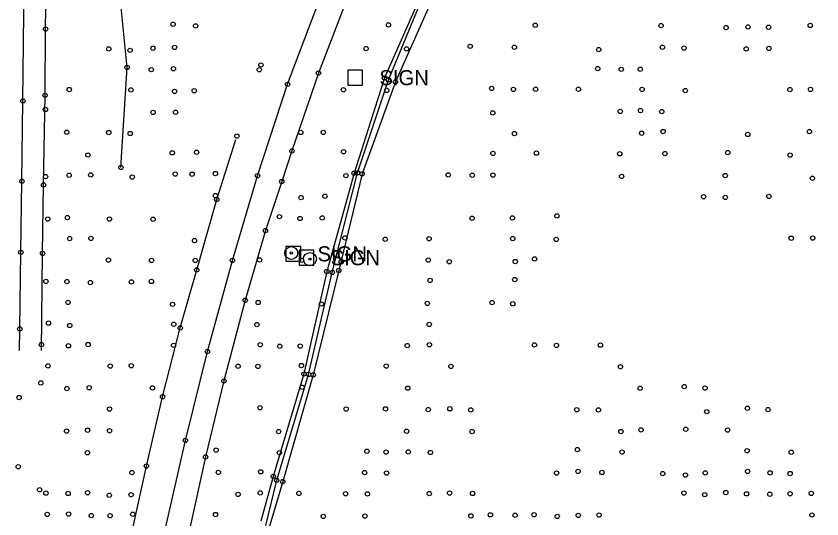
# Model space of a CAD drawing. Extents: x 20503438 to 20508873, y 7964251 to 7984667.
# Drawn here: x 20506713.1 to 20507086.3, y 7969482.5 to 7969715.3 of the extents above; entities that cross this region are included whole.
import ezdxf

# ---------------------------------------------------------------- set-up
doc = ezdxf.new("R2010")
doc.units = 0
for name, color, linetype in [('SurBreakLine', 7, 'Continuous'), ('SurConcreteSlab', 7, 'Continuous'), ('SurDrainageArrowDown', 7, 'Continuous'), ('SurEdgeRoadPaved', 7, 'Continuous'), ('SurEdgeShoulderPaved', 7, 'Continuous'), ('SurRoadPoints', 7, 'Continuous'), ('SurSurveyPoints', 7, 'Continuous')]:
    doc.layers.add(name, color=color, linetype=linetype)

msp = doc.modelspace()

# ---------------------------------------------------------------- linework, layer by layer
at = {"layer": 'SurBreakLine'}
for points in [[(20507072.22, 7970031.81), (20507044.65, 7969983.45), (20507017.24, 7969942.09), (20506993.08, 7969899.77), (20506969.73, 7969857.18), (20506943.8, 7969809.14), (20506917.86, 7969765.01), (20506900.22, 7969724.24), (20506883.74, 7969686.63), (20506869.66, 7969642.53), (20506857.03, 7969597), (20506846.45, 7969549.54), (20506832.21, 7969502.12), (20506826.5, 7969481.38)], [(20507077.67, 7970029.62), (20507050.22, 7969980.63), (20507024.17, 7969937.47), (20506998.98, 7969896.23), (20506975.04, 7969854.03), (20506947.28, 7969804.04), (20506923.35, 7969761.61), (20506905.03, 7969721.23), (20506888.8, 7969684.78), (20506873.33, 7969642.22), (20506862.58, 7969597.47), (20506850.72, 7969549.13), (20506836.64, 7969499.73), (20506830.12, 7969478.04)]]:
    msp.add_lwpolyline(points, dxfattribs=at)
at = {"layer": 'SurConcreteSlab'}
for points in [[(20506782.03, 7969476.8), (20506791.56, 7969518.77), (20506801.71, 7969559.92), (20506813.33, 7969602.11), (20506824.94, 7969641.33), (20506838.85, 7969683.67), (20506855.36, 7969727.47), (20506871.04, 7969767.26), (20506887.39, 7969806.48), (20506907.03, 7969849.3), (20506926.87, 7969889.92), (20506946.4, 7969927.42), (20506964.13, 7969959.84), (20506998.31, 7970022.29), (20507028.85, 7970078.15), (20507050.93, 7970118.98), (20507063.43, 7970141.95), (20507094.89, 7970195.02), (20507112.55, 7970224.35), (20507146.84, 7970287.64), (20507180.2, 7970349.4), (20507227.5, 7970437.73), (20507263.67, 7970507.83), (20507275.78, 7970531.85)], [(20507015.79, 7970022.74), (20506988.66, 7969972.82), (20506974.4, 7969946.87), (20506957.8, 7969916.38), (20506943.98, 7969890.96), (20506942.58, 7969888.39), (20506939.78, 7969883.25), (20506912.31, 7969832.46), (20506905.2, 7969817.2), (20506894.52, 7969794.31), (20506880.24, 7969759.41), (20506853.16, 7969688.88), (20506840.87, 7969652.86), (20506836.17, 7969638.67), (20506828.63, 7969615.96), (20506819.26, 7969583.67), (20506809.41, 7969546.3), (20506800.9, 7969511.15), (20506793, 7969475.34)]]:
    msp.add_lwpolyline(points, dxfattribs=at)
at = {"layer": 'SurDrainageArrowDown'}
for points in [[(20506828.82, 7969479.38), (20506833.81, 7969500.36), (20506848.56, 7969549.36), (20506859.54, 7969596.56), (20506871.26, 7969642.69), (20506885.58, 7969685.72), (20506901.36, 7969723.92), (20506920.9, 7969764.04), (20506945.51, 7969806.46), (20506972.6, 7969855.74), (20506995.89, 7969898.43), (20507018.3, 7969939.97), (20507047.05, 7969981.99), (20507075.27, 7970030.65)], [(20506761.69, 7969645.23), (20506764.56, 7969691.5), (20506761.66, 7969720.78), (20506764.19, 7969744.34), (20506759.83, 7969777.16), (20506761.22, 7969804.86), (20506759.8, 7969808.78)]]:
    msp.add_lwpolyline(points, dxfattribs=at)
at = {"layer": 'SurEdgeRoadPaved'}
for points in [[(20506714.74, 7969560.48), (20506714.85, 7969570.39), (20506715.33, 7969605.88), (20506715.81, 7969638.76), (20506716.28, 7969675.96), (20506717.2, 7969756.94), (20506719.24, 7969896.39), (20506719.85, 7969929.2), (20506720.11, 7969965.27), (20506721.13, 7970039.55), (20506722.02, 7970119.02), (20506722.6, 7970160.01), (20506723.54, 7970238.37), (20506726.14, 7970441.14), (20506726.38, 7970498)], [(20506730.9, 7969201.09), (20506733.07, 7969218.01), (20506735.49, 7969243.95), (20506738.88, 7969278.04), (20506741.18, 7969305.34), (20506743.92, 7969334.12), (20506747.82, 7969365.54), (20506752.03, 7969394.27), (20506757.2, 7969423.22), (20506762.29, 7969452.03), (20506763.88, 7969460.71), (20506767.14, 7969478.13), (20506773.47, 7969506.9), (20506780.98, 7969539.02), (20506789.14, 7969570.88), (20506796.77, 7969597.72), (20506806.03, 7969630.34), (20506814.9, 7969658.15)]]:
    msp.add_lwpolyline(points, dxfattribs=at)
at = {"layer": 'SurEdgeShoulderPaved'}
msp.add_lwpolyline([(20506724.86, 7969560.35), (20506725.37, 7969605.39), (20506725.83, 7969637.07), (20506726.56, 7969678.57), (20506726.78, 7969709.27), (20506727.39, 7969748.8), (20506727.68, 7969777.44), (20506728.18, 7969817.55), (20506728.65, 7969849.96), (20506728.99, 7969872.97), (20506729.53, 7969910.56), (20506729.92, 7969937.04), (20506730.73, 7969994.63), (20506730.88, 7970017.95), (20506730.93, 7970026.7), (20506731.34, 7970056.08), (20506731.9, 7970099.97), (20506732.05, 7970117.72), (20506732.39, 7970147.22), (20506732.77, 7970170.72), (20506732.8, 7970173.52), (20506734.03, 7970279.66), (20506736.01, 7970427.72), (20506736.83, 7970497.86)], dxfattribs=at)
at = {"layer": 'SurRoadPoints'}
for points in [[(20506870.19, 7969683.34), (20506870.19, 7969683.34), (20506873.62, 7969683.34), (20506873.62, 7969690.2), (20506866.76, 7969690.2), (20506866.76, 7969683.34), (20506870.19, 7969683.34)], [(20506841.52, 7969601.76), (20506841.52, 7969601.76), (20506844.95, 7969601.76), (20506844.95, 7969608.62), (20506838.09, 7969608.62), (20506838.09, 7969601.76), (20506841.52, 7969601.76)], [(20506847.58, 7969599.99), (20506847.58, 7969599.99), (20506851.01, 7969599.99), (20506851.01, 7969606.85), (20506844.15, 7969606.85), (20506844.15, 7969599.99), (20506847.58, 7969599.99)]]:
    msp.add_lwpolyline(points, dxfattribs=at)
for centre, radius in [((20506840.57, 7969605.57), 3), ((20506840.57, 7969605.57), 0.5), ((20506849.2, 7969602.73), 3), ((20506849.2, 7969602.73), 0.5)]:
    msp.add_circle(centre, radius, dxfattribs=at)
at = {"layer": 'SurSurveyPoints'}
for centre in [(20506726.78, 7969709.27), (20506785.84, 7969711.46), (20506796.24, 7969710.74), (20506885.6, 7969711.19), (20506953.53, 7969711.01), (20507011.82, 7969710.85), (20507041.94, 7969709.93), (20507052.09, 7969710.28), (20507061.61, 7969710.1), (20507080.94, 7969710.92), (20506776.53, 7969700.41), (20506786.52, 7969700.75), (20506923.43, 7969701.26), (20506943.93, 7969700.86), (20507012.45, 7969700.84), (20507022.49, 7969700.47), (20506756.06, 7969700.08), (20506765.92, 7969699.41), (20506875.22, 7969700.23), (20506894, 7969700.09), (20506982.96, 7969699.73), (20507051.25, 7969700.09), (20507061.76, 7969700.32), (20506764.56, 7969691.5), (20506775.75, 7969690.46), (20506785.97, 7969690.91), (20506825.72, 7969690.44), (20506826.51, 7969692.62), (20506982.53, 7969690.93), (20506993.4, 7969690.61), (20507002.21, 7969690.66), (20506853.16, 7969688.88), (20506883.74, 7969686.63), (20506885.58, 7969685.72), (20506838.85, 7969683.67), (20506888.8, 7969684.78), (20506933.38, 7969681.76), (20506726.56, 7969678.57), (20506737.78, 7969681.27), (20506766.34, 7969681.07), (20506786.53, 7969680.37), (20506795.6, 7969680.69), (20506864.7, 7969681.18), (20506884.77, 7969680.87), (20506943.47, 7969681.34), (20506953.7, 7969681.36), (20506973.54, 7969681.36), (20507003.02, 7969681.3), (20507023.01, 7969680.78), (20507071.53, 7969681.23), (20507081.03, 7969681.31), (20506716.28, 7969675.96), (20506726.69, 7969672.02), (20506776.6, 7969670.64), (20506787.02, 7969670.72), (20506992.94, 7969671.13), (20507002.3, 7969671.48), (20507012.16, 7969671.07), (20506933.89, 7969670.44), (20506736.58, 7969661.49), (20506756.04, 7969661.36), (20506765.96, 7969660.9), (20506815.4, 7969659.72), (20506844.94, 7969661.37), (20506855.36, 7969661.42), (20506943.89, 7969660.87), (20507002.84, 7969661.05), (20507012.78, 7969661.82), (20507051.96, 7969660.45), (20507080.52, 7969661.81), (20506785.45, 7969651.95), (20506796.74, 7969652.19), (20506840.87, 7969652.86), (20506864.79, 7969652.46), (20507042.72, 7969652.04), (20506746.36, 7969650.95), (20506933.96, 7969651.66), (20506954.08, 7969651.8), (20506992.68, 7969651.49), (20507013.61, 7969651.61), (20507071.56, 7969650.89), (20506761.69, 7969645.23), (20506726.81, 7969640.97), (20506737.71, 7969641.56), (20506747.72, 7969641.74), (20506766.9, 7969640.73), (20506786.83, 7969642.14), (20506794.64, 7969642.06), (20506805.44, 7969642.37), (20506824.94, 7969641.33), (20506865.9, 7969641.38), (20506869.66, 7969642.53), (20506871.26, 7969642.69), (20506873.33, 7969642.22), (20506913.3, 7969641.7), (20506924.39, 7969641.59), (20506933.96, 7969641.63), (20506993.54, 7969641.06), (20507041.53, 7969641.43), (20506715.81, 7969638.76), (20506725.83, 7969637.07), (20506836.17, 7969638.67), (20507081.9, 7969640.19), (20506805.43, 7969632.15), (20506806.03, 7969630.34), (20506845.14, 7969631.2), (20506856.17, 7969631.87), (20507031.5, 7969631.62), (20507041.58, 7969631.31), (20507061.79, 7969631.76), (20506736.87, 7969621.99), (20506835.09, 7969622.39), (20506963.57, 7969622.71), (20506727.77, 7969621.25), (20506756.34, 7969621.27), (20506776.56, 7969621.19), (20506844.66, 7969621.54), (20506854.93, 7969621.83), (20506924.28, 7969621.63), (20506942.99, 7969621.81), (20506828.63, 7969615.96), (20506737.94, 7969612.24), (20506747.77, 7969612.3), (20506795.75, 7969611.32), (20506865.41, 7969612.56), (20506884.08, 7969611.96), (20506904.41, 7969612.18), (20506943.14, 7969612.22), (20506963.3, 7969611.85), (20507072.11, 7969612.43), (20507082.08, 7969612.49), (20506715.33, 7969605.88), (20506725.37, 7969605.39), (20506755.91, 7969602.3), (20506775.91, 7969602.11), (20506796.11, 7969602.16), (20506813.33, 7969602.11), (20506825.88, 7969602.38), (20506845.38, 7969602.18), (20506863.73, 7969601.48), (20506904, 7969602.29), (20506913.73, 7969601.51), (20506944.27, 7969601.62), (20506953.22, 7969602.84), (20506796.77, 7969597.72), (20506857.03, 7969597), (20506859.54, 7969596.56), (20506862.58, 7969597.47), (20506726.93, 7969592.41), (20506736.69, 7969592.33), (20506766.51, 7969592.15), (20506775.79, 7969592.38), (20506904.89, 7969592.89), (20506944.08, 7969593.27), (20506747.53, 7969591.89), (20506737.19, 7969582.69), (20506785.57, 7969581.8), (20506819.26, 7969583.67), (20506825.24, 7969582.65), (20506854.55, 7969581.95), (20506903.58, 7969582.24), (20506933.56, 7969582.63), (20506943.17, 7969582.04), (20506714.85, 7969570.39), (20506728.17, 7969573.09), (20506737.98, 7969572), (20506786.17, 7969572.57), (20506789.14, 7969570.88), (20506824.66, 7969572.39), (20506904.44, 7969572.53), (20506724.89, 7969563.14), (20506737.37, 7969562.59), (20506746.47, 7969563.19), (20506786.06, 7969562.81), (20506826.22, 7969563.09), (20506835.22, 7969562.4), (20506844.7, 7969562.48), (20506894.26, 7969562.71), (20506904.57, 7969563.06), (20506953.17, 7969562.98), (20506963.39, 7969562.79), (20506983.76, 7969562.9), (20506801.71, 7969559.92), (20506727.9, 7969553.27), (20506756.74, 7969553.21), (20506766.46, 7969553.37), (20506815.95, 7969553.11), (20506825.11, 7969553.07), (20506845.24, 7969553.47), (20506884.55, 7969553.2), (20506914.5, 7969553.05), (20506993.02, 7969552.93), (20506846.45, 7969549.54), (20506848.56, 7969549.36), (20506850.72, 7969549.13), (20506724.59, 7969545.39), (20506809.41, 7969546.3), (20507022.57, 7969543.68), (20506736.69, 7969542.81), (20506746.97, 7969543.2), (20506776.29, 7969543.11), (20506845.6, 7969543.39), (20506894.49, 7969542.98), (20507002.13, 7969542.95), (20507032.23, 7969543.02), (20506714.49, 7969538.65), (20506780.98, 7969539.02), (20506756.39, 7969533.27), (20506826.09, 7969533.9), (20506865.99, 7969533.32), (20506884.26, 7969533.4), (20506904, 7969533.03), (20506914, 7969533.42), (20506923.72, 7969532.89), (20506972.8, 7969533.01), (20506982.78, 7969532.88), (20507051.84, 7969533.69), (20507061.35, 7969533.07), (20507032.99, 7969532.1), (20506736.54, 7969523.09), (20506746.24, 7969523.52), (20506756.4, 7969523.27), (20506834.73, 7969522.9), (20506893.98, 7969523.02), (20506924.34, 7969522.86), (20506993.21, 7969522.91), (20507002.59, 7969523.67), (20507023.25, 7969523.93), (20507042.64, 7969523.56), (20506791.56, 7969518.77), (20506805.78, 7969514.31), (20506973.06, 7969514.52), (20507051.63, 7969513.99), (20506746.13, 7969513.06), (20506800.9, 7969511.15), (20506835.1, 7969513.1), (20506875.57, 7969513.76), (20506884.48, 7969513.4), (20506894.76, 7969513.45), (20506905.03, 7969513.19), (20506993.77, 7969513.36), (20507072.14, 7969513.3), (20506714.14, 7969506.57), (20506773.47, 7969506.9), (20506766.8, 7969503.87), (20506806.85, 7969504), (20506826.46, 7969504.24), (20506874.52, 7969503.88), (20506884.71, 7969503.65), (20506963.43, 7969503.69), (20506973.41, 7969504.46), (20506984.45, 7969503.94), (20507012.58, 7969503.43), (20507023.11, 7969502.75), (20507032.29, 7969503.72), (20507051.91, 7969504.43), (20507062.32, 7969503.77), (20507071.58, 7969503.46), (20506832.21, 7969502.12), (20506833.81, 7969500.36), (20506836.64, 7969499.73), (20506723.99, 7969495.92), (20506726.96, 7969494.37), (20506737.24, 7969494.21), (20506746.21, 7969494.54), (20506756.24, 7969493.39), (20506766.39, 7969493.64), (20506815.91, 7969493.76), (20506826.19, 7969494.48), (20506844.12, 7969494.26), (20506865.73, 7969494.11), (20506875.86, 7969494), (20506904.49, 7969494.19), (20506913.9, 7969494.38), (20506924.51, 7969494.21), (20507022.44, 7969494.41), (20507032.08, 7969493.67), (20507041.81, 7969494.66), (20507051.4, 7969494.05), (20507062.2, 7969493.86), (20507071.58, 7969494.07), (20507081.35, 7969494.24), (20506727.58, 7969484.53), (20506737.45, 7969484.69), (20506747.94, 7969483.98), (20506756.65, 7969483.93), (20506767.19, 7969484.59), (20506805.55, 7969484.47), (20506932.81, 7969484.33), (20506944.21, 7969484.12), (20506953.04, 7969484.36), (20506973.48, 7969484.07), (20506983.09, 7969484.24), (20507081.67, 7969484.25), (20506855.41, 7969483.59), (20506874.69, 7969483.75), (20506923.79, 7969483.86), (20506963.74, 7969483.62)]:
    msp.add_circle(centre, 1, dxfattribs=at)

# ---------------------------------------------------------------- texts
at = {"layer": 'SurRoadPoints'}
for p in [(20506881.4, 7969683.27), (20506852.73, 7969601.69), (20506858.79, 7969599.92)]:
    msp.add_text('SIGN', height=6.995, rotation=360, dxfattribs=at).set_placement(p)

doc.saveas('drawing.dxf')
